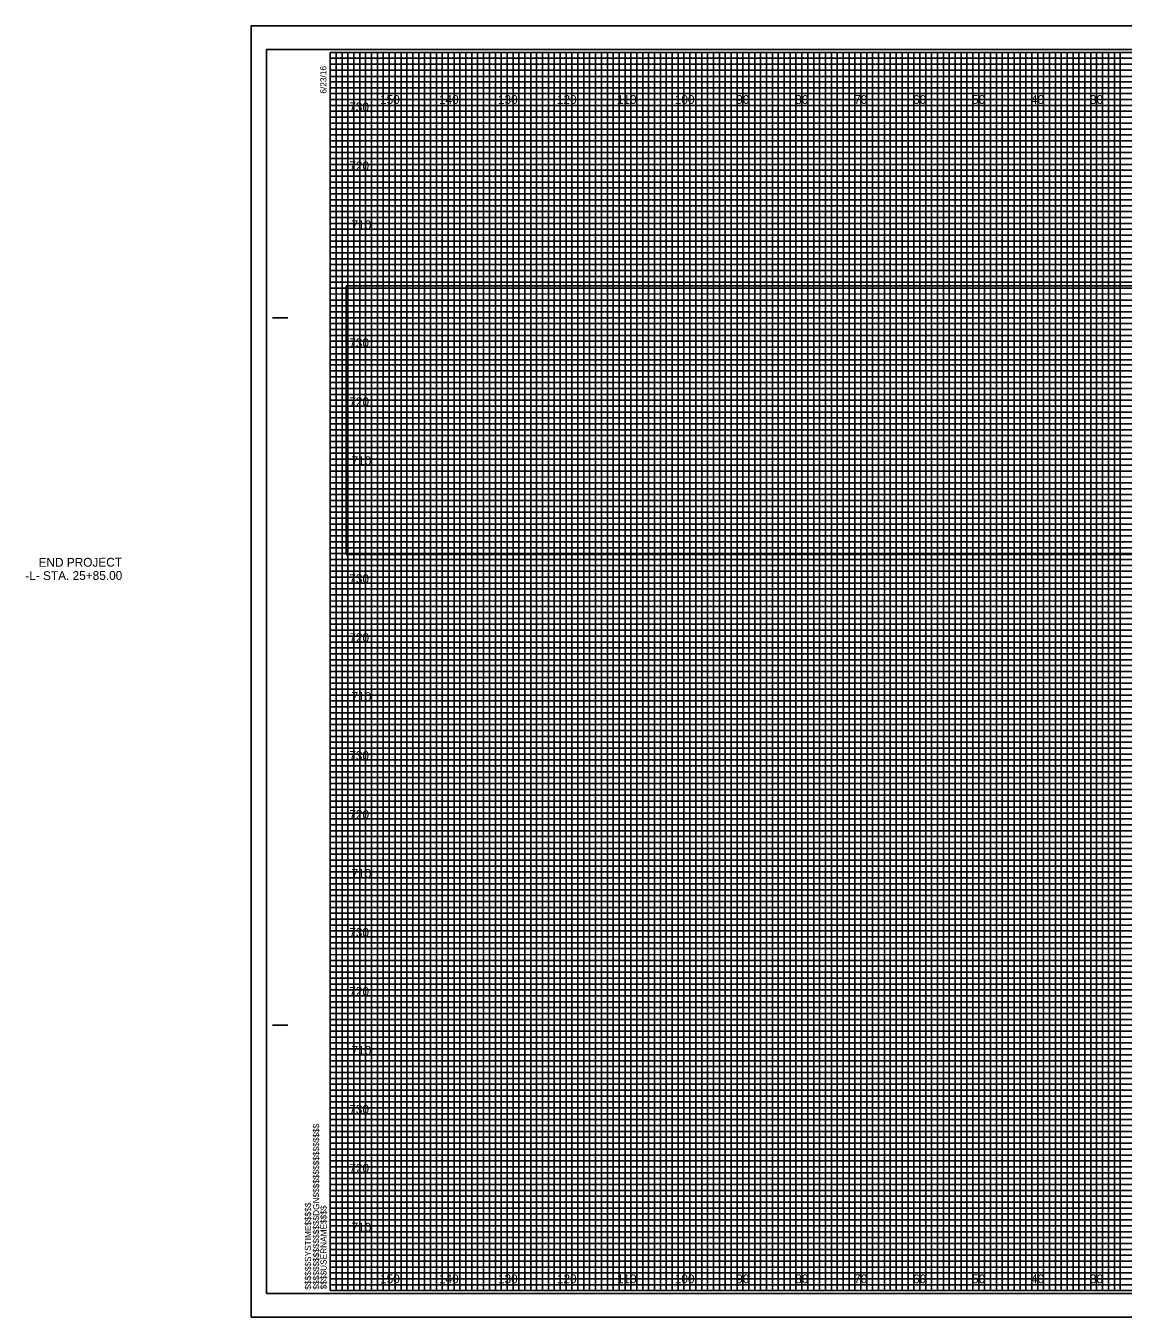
# Model space of a CAD drawing. Extents: x -98 to 717, y -10 to 1974.
# Drawn here: x -51.6 to 134.5, y 1535.5 to 1754.5 of the extents above; entities that cross this region are included whole.
import ezdxf

# ---------------------------------------------------------------- set-up
doc = ezdxf.new("R2010")
doc.units = 0
for name, color, linetype in [('Default', 7, 'Continuous'), ('Exist XS Center Line Elevation Label', 7, 'Continuous'), ('Prop CMT Conc Surface', 7, 'Continuous'), ('Prop CMT Concrete Structures', 7, 'Continuous'), ('Prop CMT Pvmt Course 1 CG', 7, 'Continuous'), ('Prop CMT Pvmt Course 2', 7, 'Continuous'), ('Prop CMT Pvmt Course 3', 7, 'Continuous'), ('Prop CMT Pvmt Surface', 7, 'Continuous'), ('Prop CMT Subgrade Earthwork', 7, 'Continuous'), ('Prop XS Ditch Standard Text', 7, 'Continuous'), ('Prop XS Dump Level', 7, 'Continuous'), ('Prop XS Earthwork Shape', 7, 'Continuous'), ('Prop XS Elevation Labels', 7, 'Continuous'), ('Typical Curb CELL', 7, 'Continuous')]:
    doc.layers.add(name, color=color, linetype=linetype)

msp = doc.modelspace()

# ---------------------------------------------------------------- linework, layer by layer
at = {"layer": 'Default'}
msp.add_lwpolyline([(-13.4, 1535.5), (323.3, 1535.5), (323.3, 1754.5), (-13.4, 1754.5)], close=True, dxfattribs=at)
at = {"layer": 'Exist XS Center Line Elevation Label'}
for p, q in [((0, 1749), (260, 1749)), ((260, 1747.98), (0, 1747.98)), ((0, 1747.98), (0, 1747)), ((0, 1747), (260, 1747)), ((260, 1745.89), (0, 1745.89)), ((0, 1745.89), (0, 1744)), ((0, 1744), (320, 1744))]:
    msp.add_line(p, q, dxfattribs=at)
for points in [[(0, 1743), (270, 1743), (320, 1743), (320, 1742), (0, 1742)], [(0, 1741), (320, 1741), (320, 1739), (0, 1739)], [(0, 1738), (320, 1738), (320, 1737), (0, 1736.98)], [(0, 1736), (320, 1736), (320, 1734), (0, 1734)], [(0, 1733), (320, 1733), (320, 1732), (0, 1732)], [(0, 1731), (320, 1731), (320, 1729), (0, 1729)], [(0, 1728), (320, 1728), (320, 1727), (0, 1727)], [(0, 1726), (320, 1726), (320, 1724), (0, 1724)], [(0, 1723), (320, 1723), (320, 1722), (0, 1722)], [(0, 1721), (320, 1721), (320, 1719), (0, 1719)], [(0, 1718), (320, 1718), (320, 1717), (0, 1717)], [(0, 1716), (320, 1716), (320, 1713.95), (320, 1713), (320, 1712), (0, 1712)], [(0, 1714), (320, 1714), (320, 1713), (0, 1713)], [(0, 1711), (320, 1711), (320, 1709), (0, 1709.03)], [(0, 1709.03), (320, 1709), (320, 1708), (0, 1708)], [(0, 1707), (320, 1707), (320, 1706), (0, 1706)], [(0, 1704), (320, 1704), (320, 1703), (0, 1703)], [(0, 1702), (320, 1702), (320, 1701), (0, 1701)], [(-0.07, 1698.89), (320, 1698.89), (320, 1697.88), (-0.07, 1697.88)], [(0, 1697), (320, 1697), (320, 1696), (0, 1696)], [(0, 1694), (320, 1694), (320, 1693), (0, 1693)], [(0, 1692), (320, 1692), (320, 1691), (0, 1691)], [(0, 1689), (320, 1689), (320, 1688), (0, 1688)], [(0, 1687), (320, 1687), (320, 1686), (0, 1686)], [(0, 1684), (320, 1684), (320, 1683), (0, 1683)], [(0, 1682), (320, 1682), (320, 1681), (0, 1681)], [(0, 1679), (320, 1679), (319.99, 1677.98), (0, 1678)], [(0, 1677), (320, 1677), (320, 1676), (0, 1676)], [(0, 1674), (320, 1674), (320, 1673), (0, 1673)], [(0, 1672), (320, 1672), (320, 1671), (0, 1671)], [(0, 1669), (320, 1669), (320, 1668), (0, 1668)], [(0, 1667), (320, 1667), (320, 1666), (0, 1666)], [(0, 1664), (320, 1664), (320, 1663), (0, 1663)], [(0, 1662), (320, 1662), (320, 1661), (0, 1661)], [(0, 1659), (320, 1659), (320, 1658), (0, 1658)], [(0, 1656.99), (320.07, 1656.91), (320, 1656), (0, 1656)], [(0, 1654), (320, 1654), (320, 1653), (0, 1653)], [(0, 1652), (320, 1652), (320, 1651), (0, 1651)], [(0, 1649), (320, 1649), (320, 1648), (0, 1648)], [(0, 1647), (320, 1647), (320, 1646), (0, 1646)], [(0, 1644), (320, 1644), (320, 1643), (0, 1643)], [(0, 1642), (320, 1642), (320, 1641), (0, 1641)], [(0, 1639), (320, 1639), (320, 1638), (0, 1638)], [(0, 1637), (320, 1637), (320, 1636), (0, 1636)], [(0, 1634), (320, 1634), (320, 1633), (0, 1633)], [(0, 1632), (320, 1632), (320, 1631), (0, 1631)], [(0, 1629), (320, 1629), (320, 1628), (0, 1628)], [(0, 1627), (320, 1627), (320, 1626), (0, 1626)], [(0, 1624), (320, 1624), (320, 1623), (0, 1623)], [(0, 1622), (320, 1622), (320, 1621), (0, 1621)], [(0, 1619), (320, 1619), (319.99, 1617.98), (0, 1618)], [(0, 1617), (320, 1617), (320, 1616), (0, 1616)], [(0, 1614), (320, 1614), (320, 1613), (0, 1613)], [(0, 1612), (320, 1612), (320, 1611), (0, 1611)], [(0, 1609), (320, 1609), (320, 1608), (0, 1608)], [(0, 1607), (320, 1607), (320, 1606), (0, 1606)], [(0, 1604), (320, 1604), (320, 1603), (0, 1603)], [(0, 1602), (320, 1602), (320, 1601), (0, 1601)], [(0, 1599), (320, 1599), (320, 1598), (0, 1598)], [(0, 1596.99), (320.07, 1596.91), (320, 1596), (0, 1596)], [(0, 1594), (320, 1594), (320, 1593), (0, 1593)], [(0, 1592), (320, 1592), (320, 1591), (0, 1591)], [(0, 1589), (320, 1589), (320, 1588), (0, 1588)], [(0, 1587), (320, 1587), (320, 1586), (0, 1586)], [(0, 1584), (320, 1584), (320, 1583), (0, 1583)], [(0, 1582), (320, 1582), (320, 1581), (0, 1581)], [(0, 1579), (320, 1579), (320, 1578), (0, 1578)], [(0, 1577), (320, 1577), (320, 1576), (0, 1576)], [(0, 1574), (320, 1574), (320, 1573), (0, 1573)], [(0, 1572), (320, 1572), (320, 1571), (0, 1571)], [(0, 1569), (320, 1569), (320, 1568), (0, 1568)], [(0, 1567), (320, 1567), (320, 1566), (0, 1566)], [(0, 1564), (320, 1564), (320, 1563), (0, 1563)], [(0, 1562), (320, 1562), (320, 1561), (0, 1561)], [(0, 1559), (320, 1559), (320, 1558), (0, 1558)], [(0, 1557), (320, 1557), (320, 1556), (0, 1556)], [(0, 1554), (320, 1554), (320, 1553), (0, 1553)], [(0, 1552), (320, 1552), (320, 1551), (0, 1551)], [(0, 1549), (320, 1549), (320, 1548), (0, 1548)], [(0, 1547), (320, 1547), (320, 1546), (0, 1546)], [(0, 1544), (320, 1544), (320, 1543), (0, 1543)], [(0, 1542), (320, 1542), (320, 1541), (0, 1541)]]:
    msp.add_lwpolyline(points, dxfattribs=at)
at = {"layer": 'Prop CMT Conc Surface'}
for p, q in [((-9.8, 1705), (-7.3, 1705)), ((-9.7, 1705), (-7.2, 1705)), ((-9.8, 1585), (-7.3, 1585)), ((-9.7, 1585), (-7.2, 1585)), ((0, 1540), (0, 1540)), ((0, 1540), (0, 1540)), ((0, 1540), (0, 1540)), ((0, 1540), (0, 1540)), ((0, 1540), (0, 1540)), ((0, 1540), (0, 1540)), ((0, 1540), (0, 1540))]:
    msp.add_line(p, q, dxfattribs=at)
msp.add_lwpolyline([(320, 1750), (0, 1750), (0, 1540), (320, 1540)], close=True, dxfattribs=at)
at = {"layer": 'Prop CMT Concrete Structures'}
for p, q in [((10, 1540), (10, 1750)), ((20, 1540), (20, 1750)), ((30, 1540), (30, 1750)), ((40, 1540), (40, 1750)), ((50, 1540), (50, 1750)), ((60, 1540), (60, 1750)), ((70, 1540), (70, 1750)), ((80, 1540), (80, 1750)), ((90, 1540), (90, 1750)), ((100, 1540), (100, 1750)), ((110, 1540), (110, 1750)), ((120, 1540), (120, 1750)), ((130, 1540), (130, 1750)), ((0, 1740), (320, 1740)), ((0, 1730), (320, 1730)), ((0, 1720), (320, 1720)), ((0, 1710), (320, 1710)), ((0, 1700), (320, 1700)), ((0, 1690), (320, 1690)), ((0, 1680), (320, 1680)), ((0, 1670), (320, 1670)), ((0, 1660), (320, 1660)), ((0, 1650), (320, 1650)), ((0, 1640), (320, 1640)), ((0, 1630), (320, 1630)), ((0, 1620), (320, 1620)), ((0, 1610), (320, 1610)), ((0, 1600), (320, 1600)), ((0, 1590), (320, 1590)), ((0, 1580), (320, 1580)), ((0, 1570), (320, 1570)), ((0, 1560), (320, 1560)), ((0, 1550), (320, 1550))]:
    msp.add_line(p, q, dxfattribs=at)
at = {"layer": 'Prop CMT Pvmt Course 2'}
msp.add_lwpolyline([(-13.4, 1535.5), (323.3, 1535.5), (323.3, 1754.5), (-13.4, 1754.5)], close=True, dxfattribs=at)
at = {"layer": 'Prop CMT Pvmt Course 3'}
msp.add_lwpolyline([(-10.8, 1539.5), (322.4, 1539.5), (322.4, 1750.5), (-10.8, 1750.5)], close=True, dxfattribs=at)
at = {"layer": 'Prop CMT Pvmt Surface'}
for p, q in [((323.3, 1754.5), (-13.4, 1754.5)), ((-13.4, 1754.5), (-13.4, 1535.5)), ((-13.4, 1535.5), (323.3, 1535.5))]:
    msp.add_line(p, q, dxfattribs=at)
at = {"layer": 'Prop CMT Subgrade Earthwork'}
for points in [[(0, 1540), (1, 1540), (1, 1750), (2, 1750), (2, 1540)], [(2, 1540), (3, 1540), (3, 1750), (4, 1750), (4, 1540)], [(5, 1540), (6, 1540), (6, 1750), (7, 1750), (7, 1540)], [(7, 1540), (8, 1540), (8, 1750), (9, 1750), (9, 1540)], [(10, 1540), (11, 1540), (11, 1750), (12, 1750), (12, 1540)], [(12, 1540), (13, 1540), (13, 1750), (14, 1750), (14, 1540)], [(15, 1540), (16, 1540), (16, 1750), (17, 1750), (17, 1540)], [(17, 1540), (18, 1540), (18, 1750), (19, 1750), (19, 1540)], [(20, 1540), (21, 1540), (21, 1750), (22, 1750), (22, 1540)], [(22, 1540), (23, 1540), (23, 1750), (24, 1750), (24, 1540)], [(25, 1540), (26, 1540), (26, 1750), (27, 1750), (27, 1540)], [(27, 1540), (28, 1540), (28, 1750), (29, 1750), (29, 1540)], [(30, 1540), (31, 1540), (31, 1750), (32, 1750), (32, 1540)], [(32, 1540), (33, 1540), (33, 1750), (34, 1750), (34, 1540)], [(35, 1540), (36, 1540), (36, 1750), (37, 1750), (37, 1540)], [(37, 1540), (38, 1540), (38, 1750), (39, 1750), (39, 1540)], [(40, 1540), (41, 1540), (41, 1750), (42, 1750), (42, 1540)], [(42, 1540), (43, 1540), (43, 1750), (44, 1750), (44, 1540)], [(45, 1540), (46, 1540), (46, 1750), (47, 1750), (47, 1540)], [(47, 1540), (48, 1540), (48, 1750), (49, 1750), (49, 1540)], [(50, 1540), (51, 1540), (51, 1750), (52, 1750), (52, 1540)], [(52, 1540), (53, 1540), (53, 1750), (54, 1750), (54, 1540)], [(55, 1540), (56, 1540), (56, 1750), (57, 1750), (57, 1540)], [(57, 1540), (58, 1540), (58, 1750), (59, 1750), (59, 1540)], [(60, 1540), (61, 1540), (61, 1750), (62, 1750), (62, 1540)], [(62, 1540), (63, 1540), (63, 1750), (64, 1750), (64, 1540)], [(65, 1540), (66, 1540), (66, 1750), (67, 1750), (67, 1540)], [(67, 1540), (68, 1540), (68, 1750), (69, 1750), (69, 1540)], [(70, 1540), (71, 1540), (71, 1750), (72, 1750), (72, 1540)], [(72, 1540), (73, 1540), (73, 1750), (74, 1750), (74, 1540)], [(75, 1540), (76, 1540), (76, 1750), (77, 1750), (77, 1540)], [(77, 1540), (78, 1540), (78, 1750), (79, 1750), (79, 1540)], [(80, 1540), (81, 1540), (81, 1750), (82, 1750), (82, 1540)], [(82, 1540), (83, 1540), (83, 1750), (84, 1750), (84, 1540)], [(85, 1540), (86, 1540), (86, 1750), (87, 1750), (87, 1540)], [(87, 1540), (88, 1540), (88, 1750), (89, 1750), (89, 1540)], [(90, 1540), (91, 1540), (91, 1750), (92, 1750), (92, 1540)], [(92, 1540), (93, 1540), (93, 1750), (94, 1750), (94, 1540)], [(95, 1540), (96, 1540), (96, 1750), (97, 1750), (97, 1540)], [(97, 1540), (98, 1540), (98, 1750), (99, 1750), (99, 1540)], [(100, 1540), (101, 1540), (101, 1750), (102, 1750), (102, 1540)], [(102, 1540), (103, 1540), (103, 1750), (104, 1750), (104, 1540)], [(105, 1540), (106, 1540), (106, 1750), (107, 1750), (107, 1540)], [(107, 1540), (108, 1540), (108, 1750), (109, 1750), (109, 1540)], [(110, 1540), (111, 1540), (111, 1750), (112, 1750), (112, 1540)], [(112, 1540), (113, 1540), (113, 1750), (114, 1750), (114, 1540)], [(115, 1540), (116, 1540), (116, 1750), (117, 1750), (117, 1540)], [(117, 1540), (118, 1540), (118, 1750), (119, 1750), (119, 1540)], [(120, 1540), (121, 1540), (121, 1750), (122, 1750), (122, 1540)], [(122, 1540), (123, 1540), (123, 1750), (124, 1750), (124, 1540)], [(125, 1540), (126, 1540), (126, 1750), (127, 1750), (127, 1540)], [(127, 1540), (128, 1540), (128, 1750), (129, 1750), (129, 1540)], [(130, 1540), (131, 1540), (131, 1750), (132, 1750), (132, 1540)], [(132, 1540), (133, 1540), (133, 1750), (134, 1750), (134, 1540)]]:
    msp.add_lwpolyline(points, dxfattribs=at)
at = {"layer": 'Prop XS Ditch Standard Text'}
msp.add_lwpolyline([(2.72, 1710.38), (314.41, 1710.38), (314.41, 1664.86), (2.72, 1664.86)], close=True, dxfattribs=at)
at = {"layer": 'Prop XS Elevation Labels'}
for p, q in [((10, 1750), (0, 1750)), ((10, 1540), (10, 1750)), ((30, 1750), (20, 1750)), ((20, 1750), (20, 1540)), ((30, 1540), (30, 1750)), ((50, 1750), (40, 1750)), ((40, 1750), (40, 1540)), ((50, 1540), (50, 1750)), ((70, 1750), (60, 1750)), ((60, 1750), (60, 1540)), ((70, 1540), (70, 1750)), ((90, 1750), (80, 1750)), ((80, 1750), (80, 1540)), ((90, 1540), (90, 1750)), ((110, 1750), (100, 1750)), ((100, 1750), (100, 1540)), ((110, 1540), (110, 1750)), ((130, 1750), (120, 1750)), ((120, 1750), (120, 1540)), ((130, 1540), (130, 1750)), ((20, 1540), (10, 1540)), ((40, 1540), (30, 1540)), ((60, 1540), (50, 1540)), ((80, 1540), (70, 1540)), ((100, 1540), (90, 1540)), ((120, 1540), (110, 1540)), ((140, 1540), (130, 1540))]:
    msp.add_line(p, q, dxfattribs=at)
for points in [[(0, 1740), (320, 1740), (320, 1730), (0, 1730)], [(0, 1720), (320, 1720), (320, 1710), (0, 1710)], [(0, 1700), (320, 1700), (320, 1690), (0, 1690)], [(0, 1680), (320, 1680), (320, 1670), (0, 1670)], [(0, 1660), (320, 1660), (320, 1650), (0, 1650)], [(0, 1640), (320, 1640), (320, 1630), (0, 1630)], [(0, 1620), (320, 1620), (320, 1610), (0, 1610)], [(0, 1600), (320, 1600), (320, 1590), (0, 1590)], [(0, 1580), (320, 1580), (320, 1570), (0, 1570)], [(0, 1560), (320, 1560), (320, 1550), (0, 1550)]]:
    msp.add_lwpolyline(points, dxfattribs=at)
at = {"layer": 'Typical Curb CELL'}
for points in [[(0, 1750), (5, 1750), (5, 1540), (15, 1540), (15, 1750), (25, 1750), (25, 1540), (35, 1540), (35, 1750), (45, 1750), (45, 1540), (55, 1540), (55, 1750), (65, 1750), (65, 1540), (75, 1540), (75, 1750), (85, 1750), (85, 1540), (95, 1540), (95, 1750), (105, 1750), (105, 1540), (115, 1540), (115, 1750), (125, 1750), (125, 1540), (135, 1540)], [(0, 1745), (275, 1745)], [(0, 1725), (320, 1725), (320, 1735), (0, 1735)], [(0, 1705), (320, 1705), (320, 1715), (0, 1715)], [(0, 1685), (320, 1685), (320, 1695), (0, 1695)], [(0, 1665), (320, 1665), (320, 1675), (0, 1675)], [(0, 1645), (320, 1645), (320, 1655), (0, 1655)], [(0, 1625), (320, 1625), (320, 1635), (0, 1635)], [(0, 1605), (320, 1605), (320, 1615), (0, 1615)], [(0, 1585), (320, 1585), (320, 1595), (0, 1595)], [(0, 1565), (320, 1565), (320, 1575), (0, 1575)], [(0, 1545), (320, 1545), (320, 1555), (0, 1555)]]:
    msp.add_lwpolyline(points, dxfattribs=at)

# ---------------------------------------------------------------- texts
at = {"layer": 'Prop CMT Conc Surface'}
for s, p in [('6/23/16', (-0.65, 1743)), ('$$$$$$$$$$$$$$$$DGN$$$$$$$$$$$$$$$$', (-1.88, 1540.18)), ('$$$$$$SYSTIME$$$$$', (-3.26, 1540.18)), ('$$$$USERNAME$$$$', (-0.62, 1540.23))]:
    msp.add_text(s, height=1.05, rotation=90, dxfattribs=at).set_placement(p)
at = {"layer": 'Prop CMT Pvmt Course 1 CG'}
for s, p in [('730', (3.22, 1740)), ('720', (3.23, 1730)), ('710', (3.61, 1720)), ('730', (3.22, 1700)), ('720', (3.23, 1690)), ('710', (3.61, 1680)), ('730', (3.22, 1660)), ('720', (3.23, 1650)), ('710', (3.61, 1640)), ('730', (3.22, 1630)), ('720', (3.23, 1620)), ('710', (3.61, 1610)), ('730', (3.22, 1600)), ('720', (3.23, 1590)), ('710', (3.61, 1580)), ('730', (3.22, 1570)), ('720', (3.23, 1560)), ('710', (3.61, 1550))]:
    msp.add_text(s, height=1.5, dxfattribs=at).set_placement(p)
at = {"layer": 'Prop XS Dump Level'}
for s, p in [('END PROJECT', (-49.48, 1662.75)), ('-L- STA. 25+85.00', (-51.73, 1660.5))]:
    msp.add_text(s, height=1.5, rotation=0.1418, dxfattribs=at).set_placement(p)
at = {"layer": 'Prop XS Earthwork Shape'}
for s, p in [('150', (8.44, 1741.25)), ('140', (18.44, 1741.25)), ('130', (28.44, 1741.25)), ('120', (38.44, 1741.25)), ('110', (48.62, 1741.25)), ('100', (58.44, 1741.25)), ('90', (68.86, 1741.25)), ('80', (78.86, 1741.25)), ('70', (88.86, 1741.25)), ('60', (98.86, 1741.25)), ('50', (108.86, 1741.25)), ('40', (118.86, 1741.25)), ('30', (128.86, 1741.25)), ('150', (8.44, 1541.25)), ('140', (18.44, 1541.25)), ('130', (28.44, 1541.25)), ('120', (38.44, 1541.25)), ('110', (48.62, 1541.25)), ('100', (58.44, 1541.25)), ('90', (68.86, 1541.25)), ('80', (78.86, 1541.25)), ('70', (88.86, 1541.25)), ('60', (98.86, 1541.25)), ('50', (108.86, 1541.25)), ('40', (118.86, 1541.25)), ('30', (128.86, 1541.25))]:
    msp.add_text(s, height=1.5, dxfattribs=at).set_placement(p)

doc.saveas('drawing.dxf')
